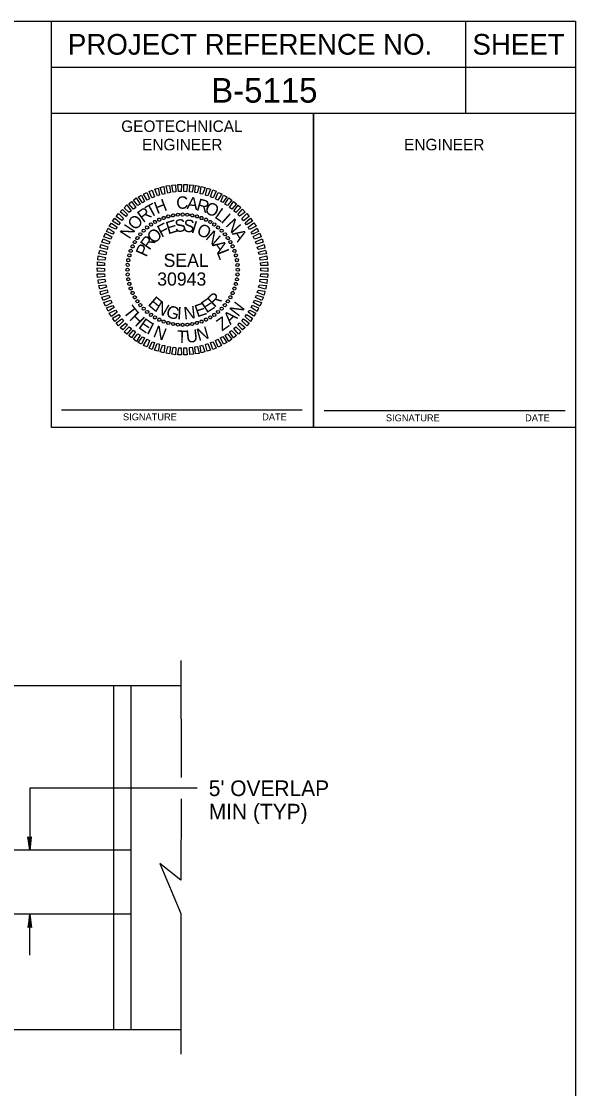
# Model space of a CAD drawing. Extents: x 2189223 to 2190097, y 563994 to 564498.
# Drawn here: x 2189792.8 to 2189877.1, y 564243.4 to 564405.9 of the extents above; entities that cross this region are included whole.
import ezdxf

# ---------------------------------------------------------------- set-up
doc = ezdxf.new("R2010")
doc.units = 0
for name, color, linetype in [('Default', 7, 'Continuous'), ('Geotech Sheets and Borders Cell', 7, 'Continuous'), ('Old_Level_2', 7, 'Continuous'), ('Old_Level_45', 7, 'Continuous'), ('Prop Seal_ PE', 7, 'Continuous')]:
    doc.layers.add(name, color=color, linetype=linetype)

msp = doc.modelspace()

# ---------------------------------------------------------------- linework, layer by layer
at = {"layer": 'Default'}
for p, q in [((2189817.07, 564308.59), (2189817.08, 564290.74)), ((2189817.07, 564304.71), (2189742.58, 564304.71)), ((2189806.81, 564304.71), (2189806.81, 564252.36)), ((2189809.42, 564304.71), (2189809.42, 564252.36)), ((2189819.54, 564289.12), (2189794.05, 564289.12)), ((2189794.05, 564289.12), (2189794.05, 564279.7)), ((2189817.08, 564287.5), (2189817.07, 564275.1)), ((2189809.42, 564279.7), (2189778.68, 564279.7)), ((2189817.07, 564275.1), (2189813.88, 564277.65)), ((2189813.88, 564277.65), (2189817.07, 564270.03)), ((2189809.42, 564269.95), (2189781.29, 564269.95)), ((2189794.05, 564263.68), (2189794.05, 564269.95)), ((2189817.07, 564270.03), (2189817.07, 564248.6)), ((2189742.58, 564252.36), (2189817.07, 564252.36))]:
    msp.add_line(p, q, dxfattribs=at)
msp.add_lwpolyline([(2189347.77, 564405.93), (2189877.15, 564405.93), (2189877.15, 564038.89), (2189347.77, 564038.89)], close=True, dxfattribs=at)
at = {"layer": 'Geotech Sheets and Borders Cell'}
for p, q in [((2189860.39, 564405.93), (2189860.39, 564391.93)), ((2189797.39, 564398.93), (2189877.15, 564398.93)), ((2189797.39, 564391.93), (2189877.15, 564391.93)), ((2189835.51, 564346.73), (2189798.87, 564346.73)), ((2189875.53, 564346.59), (2189838.89, 564346.59))]:
    msp.add_line(p, q, dxfattribs=at)
for points in [[(2189797.39, 564405.93), (2189877.15, 564405.93), (2189877.15, 564344.09), (2189797.39, 564344.09)], [(2189797.39, 564391.93), (2189837.27, 564391.93), (2189837.27, 564344.09), (2189797.39, 564344.09)], [(2189837.27, 564391.93), (2189877.15, 564391.93), (2189877.15, 564344.09), (2189837.27, 564344.09)]]:
    msp.add_lwpolyline(points, close=True, dxfattribs=at)
at = {"layer": 'Old_Level_2'}
for p, q in [((2189794.05, 564279.7), (2189793.77, 564281.74)), ((2189793.77, 564281.74), (2189794.05, 564281.48)), ((2189793.81, 564281.7), (2189794.05, 564279.7)), ((2189794.05, 564279.7), (2189793.85, 564281.66)), ((2189793.89, 564281.63), (2189794.05, 564279.7)), ((2189794.05, 564279.7), (2189793.93, 564281.59)), ((2189793.97, 564281.55), (2189794.05, 564279.7)), ((2189794.05, 564279.7), (2189794.01, 564281.51)), ((2189794.05, 564279.7), (2189794.32, 564281.74)), ((2189794.05, 564281.48), (2189794.32, 564281.74)), ((2189794.05, 564279.7), (2189794.28, 564281.7)), ((2189794.25, 564281.66), (2189794.05, 564279.7)), ((2189794.05, 564279.7), (2189794.21, 564281.63)), ((2189794.17, 564281.59), (2189794.05, 564279.7)), ((2189794.05, 564279.7), (2189794.13, 564281.55)), ((2189794.09, 564281.51), (2189794.05, 564279.7)), ((2189794.05, 564281.48), (2189794.05, 564279.7)), ((2189794.05, 564269.95), (2189793.78, 564267.9)), ((2189794.05, 564269.95), (2189793.82, 564267.94)), ((2189793.85, 564267.98), (2189794.05, 564269.95)), ((2189794.05, 564269.95), (2189793.89, 564268.02)), ((2189793.93, 564268.06), (2189794.05, 564269.95)), ((2189794.05, 564269.95), (2189793.97, 564268.09)), ((2189794.01, 564268.13), (2189794.05, 564269.95)), ((2189794.05, 564269.95), (2189794.33, 564267.9)), ((2189794.29, 564267.94), (2189794.05, 564269.95)), ((2189794.05, 564269.95), (2189794.25, 564267.98)), ((2189794.21, 564268.02), (2189794.05, 564269.95)), ((2189794.05, 564269.95), (2189794.17, 564268.06)), ((2189794.13, 564268.09), (2189794.05, 564269.95)), ((2189794.05, 564269.95), (2189794.09, 564268.13)), ((2189794.05, 564268.17), (2189794.05, 564269.95)), ((2189794.05, 564268.17), (2189793.78, 564267.9)), ((2189794.33, 564267.9), (2189794.05, 564268.17))]:
    msp.add_line(p, q, dxfattribs=at)
at = {"layer": 'Prop Seal_ PE'}
for p, q in [((2189813.13, 564375.39), (2189813.13, 564375.39)), ((2189813.77, 564375.72), (2189813.77, 564375.72)), ((2189814.44, 564376), (2189814.44, 564376)), ((2189815.15, 564376.22), (2189815.15, 564376.22)), ((2189815.86, 564376.36), (2189815.86, 564376.36)), ((2189816.59, 564376.49), (2189816.59, 564376.49)), ((2189817.32, 564376.5), (2189817.32, 564376.5)), ((2189818.07, 564376.47), (2189818.07, 564376.47)), ((2189818.79, 564376.36), (2189818.79, 564376.36)), ((2189819.49, 564376.23), (2189819.49, 564376.23)), ((2189820.2, 564376), (2189820.2, 564376)), ((2189820.88, 564375.72), (2189820.88, 564375.72)), ((2189821.53, 564375.4), (2189821.53, 564375.4)), ((2189811.37, 564374.04), (2189811.37, 564374.04)), ((2189811.92, 564374.56), (2189811.92, 564374.56)), ((2189812.5, 564374.98), (2189812.5, 564374.98)), ((2189822.14, 564374.98), (2189822.14, 564374.98)), ((2189822.73, 564374.55), (2189822.73, 564374.55)), ((2189823.27, 564374.05), (2189823.27, 564374.05)), ((2189810.03, 564372.32), (2189810.03, 564372.32)), ((2189810.44, 564372.93), (2189810.44, 564372.93)), ((2189810.89, 564373.52), (2189810.89, 564373.52)), ((2189823.78, 564373.52), (2189823.78, 564373.52)), ((2189824.21, 564372.93), (2189824.21, 564372.93)), ((2189824.6, 564372.31), (2189824.6, 564372.31)), ((2189809.42, 564370.97), (2189809.42, 564370.97)), ((2189809.71, 564371.65), (2189809.71, 564371.65)), ((2189824.95, 564371.65), (2189824.95, 564371.65)), ((2189825.23, 564370.99), (2189825.23, 564370.99)), ((2189809.06, 564369.57), (2189809.06, 564369.57)), ((2189809.2, 564370.27), (2189809.2, 564370.27)), ((2189825.44, 564370.29), (2189825.44, 564370.29)), ((2189825.59, 564369.55), (2189825.59, 564369.55)), ((2189808.92, 564368.11), (2189808.92, 564368.11)), ((2189808.95, 564367.37), (2189808.95, 564367.37)), ((2189808.96, 564368.85), (2189808.96, 564368.85)), ((2189825.69, 564367.37), (2189825.69, 564367.37)), ((2189825.7, 564368.83), (2189825.7, 564368.83)), ((2189825.74, 564368.1), (2189825.74, 564368.1)), ((2189809.06, 564366.66), (2189809.06, 564366.66)), ((2189809.21, 564365.91), (2189809.21, 564365.91)), ((2189825.44, 564365.93), (2189825.44, 564365.93)), ((2189825.59, 564366.64), (2189825.59, 564366.64)), ((2189809.41, 564365.22), (2189809.41, 564365.22)), ((2189809.7, 564364.56), (2189809.7, 564364.56)), ((2189824.94, 564364.56), (2189824.94, 564364.56)), ((2189825.24, 564365.22), (2189825.24, 564365.22)), ((2189810.05, 564363.91), (2189810.05, 564363.91)), ((2189810.43, 564363.28), (2189810.43, 564363.28)), ((2189810.88, 564362.7), (2189810.88, 564362.7)), ((2189823.76, 564362.69), (2189823.76, 564362.69)), ((2189824.21, 564363.27), (2189824.21, 564363.27)), ((2189824.61, 564363.89), (2189824.61, 564363.89)), ((2189811.38, 564362.16), (2189811.38, 564362.16)), ((2189811.91, 564361.66), (2189811.91, 564361.66)), ((2189812.51, 564361.22), (2189812.51, 564361.22)), ((2189813.12, 564360.81), (2189813.12, 564360.81)), ((2189821.52, 564360.82), (2189821.52, 564360.82)), ((2189822.15, 564361.22), (2189822.15, 564361.22)), ((2189822.73, 564361.64), (2189822.73, 564361.64)), ((2189823.27, 564362.17), (2189823.27, 564362.17)), ((2189813.77, 564360.49), (2189813.77, 564360.49)), ((2189814.44, 564360.2), (2189814.44, 564360.2)), ((2189815.15, 564359.97), (2189815.15, 564359.97)), ((2189815.87, 564359.84), (2189815.87, 564359.84)), ((2189816.58, 564359.73), (2189816.58, 564359.73)), ((2189817.32, 564359.7), (2189817.32, 564359.7)), ((2189818.07, 564359.73), (2189818.07, 564359.73)), ((2189818.78, 564359.84), (2189818.78, 564359.84)), ((2189819.5, 564359.99), (2189819.5, 564359.99)), ((2189820.2, 564360.2), (2189820.2, 564360.2)), ((2189820.87, 564360.48), (2189820.87, 564360.48))]:
    msp.add_line(p, q, dxfattribs=at)
for points in [[(2189812.66, 564379.07), (2189812.21, 564380.03), (2189812.71, 564380.24), (2189813.07, 564379.18)], [(2189813.48, 564379.35), (2189813.08, 564380.35), (2189813.59, 564380.52), (2189813.83, 564379.48)], [(2189814.28, 564379.58), (2189813.91, 564380.63), (2189814.48, 564380.76), (2189814.62, 564379.68)], [(2189815.07, 564379.78), (2189814.8, 564380.85), (2189815.34, 564380.91), (2189815.47, 564379.84)], [(2189815.88, 564379.91), (2189815.68, 564380.97), (2189816.25, 564381.05), (2189816.28, 564379.96)], [(2189816.72, 564379.99), (2189816.62, 564381.09), (2189817.16, 564381.09), (2189817.12, 564379.99)], [(2189817.52, 564379.99), (2189817.5, 564381.08), (2189818.06, 564381.08), (2189817.92, 564379.98)], [(2189818.36, 564379.95), (2189818.4, 564381.05), (2189818.97, 564380.96), (2189818.76, 564379.89)], [(2189819.17, 564379.84), (2189819.3, 564380.92), (2189819.85, 564380.84), (2189819.56, 564379.8)], [(2189820.02, 564379.68), (2189820.16, 564380.77), (2189820.74, 564380.64), (2189820.37, 564379.59)], [(2189820.83, 564379.46), (2189821.06, 564380.51), (2189821.58, 564380.35), (2189821.18, 564379.35)], [(2189821.59, 564379.18), (2189821.95, 564380.25), (2189822.42, 564380.05), (2189821.97, 564379.07)], [(2189810.49, 564377.86), (2189809.87, 564378.71), (2189810.28, 564379.03), (2189810.85, 564378.08)], [(2189811.22, 564378.3), (2189810.59, 564379.19), (2189811.09, 564379.46), (2189811.54, 564378.51)], [(2189811.93, 564378.71), (2189811.38, 564379.63), (2189811.89, 564379.88), (2189812.3, 564378.87)], [(2189822.35, 564378.88), (2189822.74, 564379.87), (2189823.27, 564379.64), (2189822.71, 564378.7)], [(2189823.12, 564378.51), (2189823.56, 564379.46), (2189824.06, 564379.19), (2189823.44, 564378.32)], [(2189823.77, 564378.06), (2189824.34, 564379.04), (2189824.8, 564378.7), (2189824.15, 564377.87)], [(2189808.66, 564376.22), (2189807.8, 564376.89), (2189808.2, 564377.28), (2189808.93, 564376.5)], [(2189809.2, 564376.82), (2189808.45, 564377.54), (2189808.85, 564377.96), (2189809.51, 564377.05)], [(2189809.87, 564377.34), (2189809.13, 564378.13), (2189809.57, 564378.5), (2189810.18, 564377.58)], [(2189824.47, 564377.57), (2189825.07, 564378.5), (2189825.52, 564378.15), (2189824.8, 564377.34)], [(2189825.12, 564377.06), (2189825.79, 564377.95), (2189826.21, 564377.55), (2189825.44, 564376.81)], [(2189825.75, 564376.49), (2189826.44, 564377.3), (2189826.85, 564376.88), (2189825.99, 564376.23)], [(2189807.59, 564374.94), (2189806.67, 564375.48), (2189806.99, 564375.97), (2189807.8, 564375.26)], [(2189808.08, 564375.58), (2189807.21, 564376.21), (2189807.57, 564376.66), (2189808.32, 564375.88)], [(2189826.34, 564375.9), (2189827.09, 564376.67), (2189827.45, 564376.21), (2189826.58, 564375.56)], [(2189826.86, 564375.25), (2189827.65, 564375.97), (2189827.98, 564375.49), (2189827.05, 564374.94)], [(2189806.72, 564373.53), (2189805.75, 564373.92), (2189805.99, 564374.45), (2189806.91, 564373.84)], [(2189807.1, 564374.26), (2189806.16, 564374.74), (2189806.48, 564375.21), (2189807.36, 564374.56)], [(2189827.28, 564374.57), (2189828.16, 564375.23), (2189828.5, 564374.73), (2189827.53, 564374.24)], [(2189827.75, 564373.84), (2189828.66, 564374.44), (2189828.89, 564373.93), (2189827.94, 564373.53)], [(2189806.07, 564372), (2189805.02, 564372.3), (2189805.24, 564372.81), (2189806.25, 564372.37)], [(2189806.39, 564372.76), (2189805.35, 564373.13), (2189805.59, 564373.65), (2189806.56, 564373.13)], [(2189828.08, 564373.14), (2189829.07, 564373.65), (2189829.3, 564373.12), (2189828.26, 564372.76)], [(2189828.4, 564372.34), (2189829.41, 564372.8), (2189829.61, 564372.29), (2189828.58, 564372)], [(2189805.63, 564370.39), (2189804.59, 564370.52), (2189804.7, 564371.09), (2189805.76, 564370.75)], [(2189805.84, 564371.2), (2189804.79, 564371.41), (2189804.9, 564371.96), (2189805.96, 564371.56)], [(2189828.68, 564371.55), (2189829.75, 564371.95), (2189829.86, 564371.4), (2189828.8, 564371.19)], [(2189828.89, 564370.75), (2189829.94, 564371.09), (2189830.07, 564370.52), (2189829, 564370.4)], [(2189805.43, 564368.73), (2189804.36, 564368.74), (2189804.38, 564369.29), (2189805.46, 564369.14)], [(2189805.51, 564369.55), (2189804.43, 564369.62), (2189804.49, 564370.2), (2189805.59, 564369.94)], [(2189829.07, 564369.95), (2189830.15, 564370.2), (2189830.21, 564369.64), (2189829.14, 564369.55)], [(2189829.17, 564369.14), (2189830.26, 564369.3), (2189830.31, 564368.73), (2189829.22, 564368.75)], [(2189805.44, 564367.89), (2189804.35, 564367.82), (2189804.34, 564368.39), (2189805.43, 564368.3)], [(2189805.47, 564367.06), (2189804.38, 564366.9), (2189804.34, 564367.47), (2189805.43, 564367.45)], [(2189829.21, 564367.47), (2189830.29, 564367.46), (2189830.27, 564366.91), (2189829.19, 564367.07)], [(2189829.21, 564368.32), (2189830.3, 564368.38), (2189830.3, 564367.81), (2189829.22, 564367.91)], [(2189805.59, 564366.26), (2189804.5, 564366), (2189804.45, 564366.58), (2189805.5, 564366.66)], [(2189805.75, 564365.45), (2189804.71, 564365.12), (2189804.58, 564365.68), (2189805.64, 564365.8)], [(2189829.02, 564365.81), (2189830.07, 564365.7), (2189829.95, 564365.13), (2189828.88, 564365.46)], [(2189829.14, 564366.67), (2189830.21, 564366.59), (2189830.16, 564366.02), (2189829.06, 564366.27)], [(2189805.96, 564364.65), (2189804.9, 564364.25), (2189804.8, 564364.8), (2189805.84, 564365.01)], [(2189806.24, 564363.86), (2189805.24, 564363.4), (2189805.04, 564363.92), (2189806.07, 564364.21)], [(2189828.57, 564364.2), (2189829.62, 564363.91), (2189829.4, 564363.39), (2189828.4, 564363.85)], [(2189828.82, 564365), (2189829.86, 564364.81), (2189829.75, 564364.24), (2189828.69, 564364.65)], [(2189806.56, 564363.07), (2189805.58, 564362.55), (2189805.35, 564363.09), (2189806.39, 564363.44)], [(2189806.91, 564362.35), (2189805.98, 564361.77), (2189805.76, 564362.28), (2189806.7, 564362.67)], [(2189827.93, 564362.68), (2189828.89, 564362.28), (2189828.66, 564361.75), (2189827.74, 564362.36)], [(2189828.25, 564363.45), (2189829.31, 564363.09), (2189829.06, 564362.57), (2189828.1, 564363.09)], [(2189807.36, 564361.64), (2189806.48, 564360.97), (2189806.15, 564361.47), (2189807.11, 564361.96)], [(2189807.81, 564360.95), (2189806.99, 564360.23), (2189806.67, 564360.71), (2189807.6, 564361.27)], [(2189827.05, 564361.27), (2189827.98, 564360.72), (2189827.65, 564360.23), (2189826.84, 564360.95)], [(2189827.54, 564361.95), (2189828.49, 564361.46), (2189828.16, 564361), (2189827.28, 564361.64)], [(2189808.32, 564360.32), (2189807.56, 564359.54), (2189807.2, 564360), (2189808.07, 564360.64)], [(2189808.92, 564359.72), (2189808.21, 564358.92), (2189807.8, 564359.32), (2189808.65, 564359.98)], [(2189809.52, 564359.14), (2189808.86, 564358.26), (2189808.44, 564358.65), (2189809.21, 564359.39)], [(2189825.44, 564359.38), (2189826.19, 564358.67), (2189825.81, 564358.26), (2189825.13, 564359.15)], [(2189825.99, 564359.99), (2189826.86, 564359.31), (2189826.44, 564358.92), (2189825.73, 564359.72)], [(2189826.57, 564360.63), (2189827.45, 564359.98), (2189827.08, 564359.55), (2189826.33, 564360.32)], [(2189810.17, 564358.63), (2189809.57, 564357.7), (2189809.13, 564358.06), (2189809.84, 564358.87)], [(2189810.87, 564358.15), (2189810.3, 564357.16), (2189809.85, 564357.52), (2189810.5, 564358.33)], [(2189811.53, 564357.71), (2189811.09, 564356.74), (2189810.58, 564357.01), (2189811.21, 564357.9)], [(2189812.31, 564357.34), (2189811.91, 564356.34), (2189811.38, 564356.57), (2189811.93, 564357.5)], [(2189822.71, 564357.5), (2189823.26, 564356.57), (2189822.76, 564356.32), (2189822.35, 564357.34)], [(2189823.43, 564357.91), (2189824.06, 564357.02), (2189823.55, 564356.74), (2189823.11, 564357.71)], [(2189824.16, 564358.35), (2189824.8, 564357.5), (2189824.36, 564357.17), (2189823.79, 564358.13)], [(2189824.79, 564358.85), (2189825.52, 564358.07), (2189825.07, 564357.7), (2189824.47, 564358.64)], [(2189813.07, 564357.03), (2189812.71, 564355.97), (2189812.23, 564356.16), (2189812.67, 564357.13)], [(2189813.82, 564356.74), (2189813.59, 564355.7), (2189813.07, 564355.85), (2189813.47, 564356.85)], [(2189814.63, 564356.54), (2189814.48, 564355.44), (2189813.91, 564355.57), (2189814.28, 564356.62)], [(2189815.48, 564356.36), (2189815.35, 564355.3), (2189814.8, 564355.37), (2189815.08, 564356.4)], [(2189816.3, 564356.24), (2189816.24, 564355.15), (2189815.68, 564355.25), (2189815.88, 564356.31)], [(2189817.12, 564356.22), (2189817.14, 564355.12), (2189816.59, 564355.13), (2189816.73, 564356.22)], [(2189817.94, 564356.2), (2189818.03, 564355.13), (2189817.49, 564355.13), (2189817.52, 564356.21)], [(2189818.77, 564356.31), (2189818.97, 564355.24), (2189818.4, 564355.17), (2189818.37, 564356.25)], [(2189819.57, 564356.42), (2189819.86, 564355.35), (2189819.31, 564355.29), (2189819.17, 564356.37)], [(2189820.36, 564356.62), (2189820.73, 564355.57), (2189820.17, 564355.45), (2189820.02, 564356.53)], [(2189821.18, 564356.85), (2189821.58, 564355.85), (2189821.06, 564355.7), (2189820.81, 564356.73)], [(2189821.99, 564357.13), (2189822.44, 564356.17), (2189821.94, 564355.96), (2189821.58, 564357.02)]]:
    msp.add_lwpolyline(points, close=True, dxfattribs=at)
for centre, major_axis in [((2189813.13, 564375.38), (-0.121, 0.209)), ((2189813.78, 564375.71), (-0.102, 0.219)), ((2189814.45, 564375.99), (-0.082, 0.227)), ((2189815.15, 564376.21), (-0.062, 0.233)), ((2189815.87, 564376.37), (-0.042, 0.237)), ((2189816.59, 564376.47), (-0.021, 0.24)), ((2189817.32, 564376.5), (0, 0.241)), ((2189818.06, 564376.47), (0.021, 0.24)), ((2189818.78, 564376.37), (0.042, 0.237)), ((2189819.5, 564376.21), (0.062, 0.233)), ((2189820.2, 564375.99), (0.082, 0.227)), ((2189820.87, 564375.71), (0.102, 0.218)), ((2189821.52, 564375.38), (0.121, 0.209)), ((2189810.89, 564373.5), (-0.185, 0.155)), ((2189811.39, 564374.04), (-0.17, 0.17)), ((2189811.93, 564374.54), (-0.155, 0.185)), ((2189812.51, 564374.98), (-0.138, 0.197)), ((2189822.14, 564374.98), (0.138, 0.197)), ((2189822.72, 564374.54), (0.155, 0.185)), ((2189823.26, 564374.04), (0.17, 0.17)), ((2189823.76, 564373.5), (0.185, 0.155)), ((2189810.05, 564372.3), (-0.209, 0.121)), ((2189810.45, 564372.92), (-0.197, 0.138)), ((2189824.2, 564372.92), (0.197, 0.138)), ((2189824.6, 564372.3), (0.209, 0.121)), ((2189809.21, 564370.28), (-0.233, 0.062)), ((2189809.43, 564370.98), (-0.227, 0.082)), ((2189809.71, 564371.65), (-0.218, 0.102)), ((2189824.94, 564371.65), (0.219, 0.102)), ((2189825.22, 564370.97), (0.227, 0.082)), ((2189825.44, 564370.28), (0.233, 0.062)), ((2189808.96, 564368.84), (-0.24, 0.021)), ((2189809.05, 564369.56), (-0.237, 0.042)), ((2189825.59, 564369.56), (0.237, 0.042)), ((2189825.69, 564368.83), (0.24, 0.021)), ((2189808.93, 564368.1), (-0.241, 0)), ((2189808.96, 564367.37), (-0.24, -0.021)), ((2189825.69, 564367.37), (0.24, -0.021)), ((2189825.72, 564368.1), (0.241, 0)), ((2189809.05, 564366.64), (-0.237, -0.042)), ((2189809.21, 564365.93), (-0.233, -0.062)), ((2189825.44, 564365.93), (0.233, -0.062)), ((2189825.59, 564366.64), (0.237, -0.042)), ((2189809.43, 564365.23), (-0.227, -0.082)), ((2189809.71, 564364.55), (-0.219, -0.102)), ((2189810.05, 564363.9), (-0.209, -0.121)), ((2189824.6, 564363.9), (0.209, -0.121)), ((2189824.94, 564364.55), (0.218, -0.102)), ((2189825.22, 564365.23), (0.227, -0.082)), ((2189810.44, 564363.29), (-0.197, -0.138)), ((2189810.89, 564362.71), (-0.185, -0.155)), ((2189811.39, 564362.16), (-0.17, -0.17)), ((2189823.26, 564362.16), (0.17, -0.17)), ((2189823.76, 564362.7), (0.185, -0.155)), ((2189824.2, 564363.29), (0.197, -0.138)), ((2189811.93, 564361.67), (-0.155, -0.185)), ((2189812.51, 564361.22), (-0.138, -0.197)), ((2189813.13, 564360.83), (-0.121, -0.209)), ((2189813.77, 564360.49), (-0.102, -0.218)), ((2189820.87, 564360.49), (0.102, -0.219)), ((2189821.52, 564360.83), (0.121, -0.209)), ((2189822.14, 564361.22), (0.138, -0.197)), ((2189822.72, 564361.67), (0.155, -0.185)), ((2189814.45, 564360.21), (-0.082, -0.227)), ((2189815.15, 564359.99), (-0.062, -0.233)), ((2189815.87, 564359.83), (-0.042, -0.237)), ((2189816.59, 564359.74), (-0.021, -0.24)), ((2189817.32, 564359.71), (0, -0.241)), ((2189818.06, 564359.74), (0.021, -0.24)), ((2189818.78, 564359.83), (0.042, -0.237)), ((2189819.5, 564359.99), (0.062, -0.233)), ((2189820.2, 564360.21), (0.082, -0.227))]:
    msp.add_ellipse(centre, major_axis=major_axis, ratio=0.999708, dxfattribs=at)

# ---------------------------------------------------------------- texts
at = {"layer": 'Default'}
for s, p in [("5' OVERLAP", (2189821.31, 564287.93)), ('MIN (TYP)', (2189821.31, 564284.37))]:
    msp.add_text(s, height=2.382, dxfattribs=at).set_placement(p)
at = {"layer": 'Geotech Sheets and Borders Cell'}
for s, p in [('PROJECT REFERENCE NO.', (2189799.86, 564400.85)), ('SHEET', (2189861.44, 564400.85))]:
    msp.add_text(s, height=3.15, rotation=360, dxfattribs=at).set_placement(p)
for s, height, p in [('GEOTECHNICAL', 1.75, (2189807.98, 564389.08)), ('ENGINEER', 1.75, (2189811.16, 564386.28)), ('ENGINEER', 1.75, (2189851.04, 564386.28)), ('SIGNATURE', 1.05, (2189808.25, 564345.16)), ('DATE', 1.05, (2189829.44, 564345.16)), ('SIGNATURE', 1.05, (2189848.27, 564345.01)), ('DATE', 1.05, (2189869.46, 564345.01))]:
    msp.add_text(s, height=height, dxfattribs=at).set_placement(p)
at = {"layer": 'Old_Level_45'}
msp.add_text('B-5115', height=3.75, dxfattribs=at).set_placement((2189821.68, 564393.55))
at = {"layer": 'Prop Seal_ PE'}
for s, height, rotation, p in [('H', 1.89, 21.0651, (2189813.43, 564376.54)), ('C', 1.89, 2.0673, (2189816.39, 564377.35)), ('A', 1.89, 352.8123, (2189817.89, 564377.38)), ('R', 1.89, 344.0075, (2189819.3, 564377.18)), ('R', 1.89, 36.611, (2189811.32, 564375.19)), ('T', 1.89, 28.6317, (2189812.36, 564375.95)), ('O', 1.89, 336.0282, (2189820.54, 564376.82)), ('L', 1.89, 325.5726, (2189822.07, 564376.09)), ('O', 1.89, 47.0666, (2189810.13, 564373.98)), ('E', 1.89, 16.5219, (2189815.11, 564373.48)), ('S', 1.89, 5.2432, (2189816.2, 564373.81)), ('S', 1.89, 353.7735, (2189817.35, 564373.92)), ('I', 1.89, 342.3037, (2189818.51, 564373.8)), ('I', 1.89, 318.3249, (2189823.04, 564375.43)), ('N', 1.89, 312.578, (2189823.74, 564374.82)), ('N', 1.89, 57.0158, (2189809.23, 564372.65)), ('O', 1.89, 42.9266, (2189812.95, 564371.93)), ('F', 1.89, 27.7188, (2189814.1, 564372.95)), ('O', 1.89, 333.9445, (2189819.32, 564373.57)), ('N', 1.89, 318.7367, (2189820.69, 564372.85)), ('A', 1.89, 302.6289, (2189824.8, 564373.61)), ('R', 1.89, 54.5327, (2189812.27, 564370.97)), ('A', 1.89, 304.2657, (2189821.77, 564371.86)), ('P', 1.89, 65.8114, (2189811.81, 564369.93)), ('SEAL', 2.008, 359.9983, (2189814.43, 564368.53)), ('L', 1.89, 291.459, (2189822.49, 564370.78)), ('E', 1.89, 319.2752, (2189811.93, 564362.77)), ('R', 1.89, 43.4797, (2189822.16, 564362.24)), ('T', 1.89, 308.1335, (2189808.18, 564361.69)), ('N', 1.89, 329.6323, (2189812.97, 564361.86)), ('G', 1.89, 340.9885, (2189814.64, 564361.01)), ('I', 1.89, 356.6995, (2189816.44, 564360.55)), ('N', 1.89, 6.0547, (2189817.57, 564360.52)), ('E', 1.89, 18.4101, (2189819.53, 564360.82)), ('E', 1.89, 33.1224, (2189820.95, 564361.42)), ('N', 1.89, 52.4492, (2189825.8, 564360.83)), ('H', 1.89, 315.7001, (2189809.1, 564360.55)), ('Z', 1.89, 35.5338, (2189823.32, 564358.68)), ('A', 1.89, 43.6445, (2189824.59, 564359.62)), ('E', 1.89, 325.1989, (2189810.46, 564359.29)), ('I', 1.89, 332.9531, (2189811.72, 564358.45)), ('N', 1.89, 338.7, (2189812.71, 564357.93)), ('N', 1.89, 15.6356, (2189819.75, 564357.2)), ('T', 1.89, 358.5982, (2189816.45, 564356.97)), ('U', 1.89, 6.1648, (2189817.93, 564356.95))]:
    msp.add_text(s, height=height, rotation=rotation, dxfattribs=at).set_placement(p)
msp.add_text('30943', height=2.009, dxfattribs=at).set_placement((2189813.46, 564365.68))

doc.saveas('drawing.dxf')
